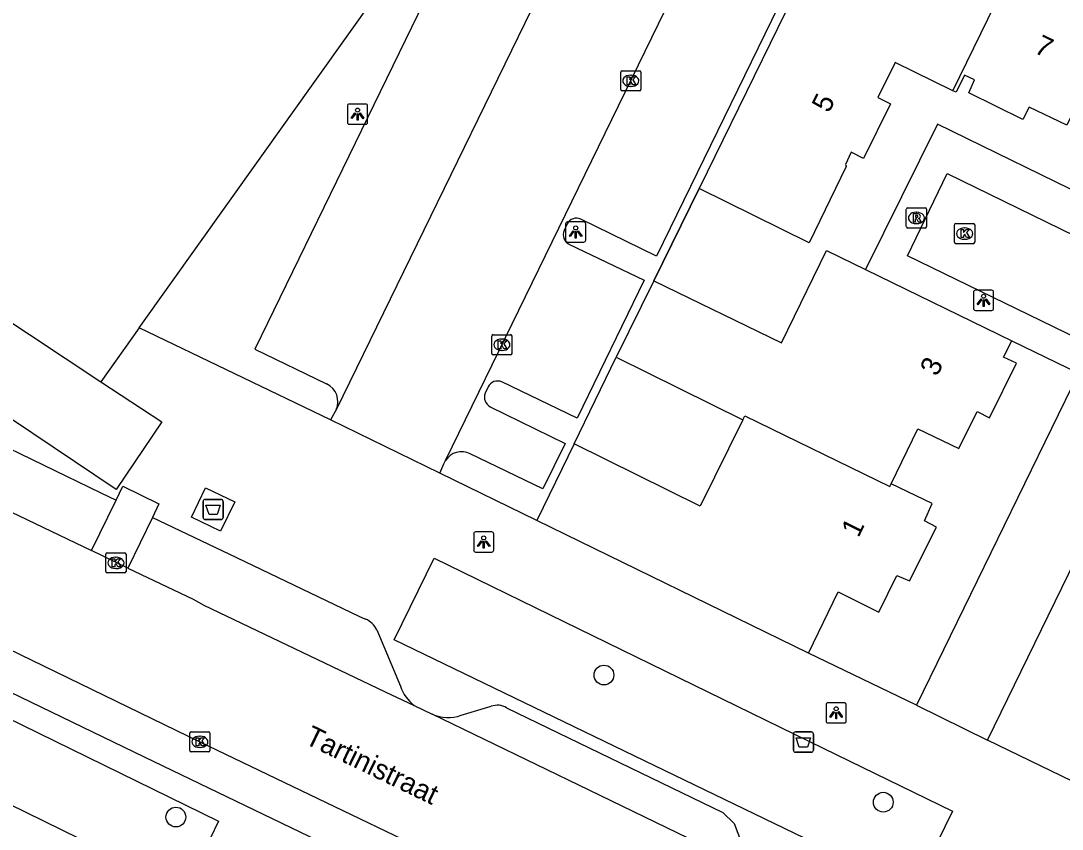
# Model space of a CAD drawing. Extents: x 159822 to 160765, y 380693 to 381634.
# Drawn here: x 160271.8 to 160323.3, y 381522.5 to 381562.5 of the extents above; entities that cross this region are included whole.
import ezdxf

# ---------------------------------------------------------------- set-up
doc = ezdxf.new("R2010")
doc.units = 0
for name, color, linetype in [('IMGEO_Afval_apart_plaats', 7, 'Continuous'), ('IMGEO_Afvalbak', 7, 'Continuous'), ('IMGEO_Boom', 7, 'Continuous'), ('IMGEO_Kolk', 7, 'Continuous'), ('IMGEO_Lichtpunt', 7, 'Continuous'), ('IMGEO_Muur', 7, 'Continuous'), ('IMGEO_Openbare_ruimte_label', 7, 'Continuous'), ('IMGEO_Pand', 7, 'Continuous'), ('IMGEO_Pand_nummerreeks', 7, 'Continuous'), ('IMGEO_Parkeervlak_gesloten', 7, 'Continuous'), ('IMGEO_Rijbaan_lokaal_open', 7, 'Continuous'), ('IMGEO_Rioolput', 7, 'Continuous'), ('IMGEO_Voetpad_gesloten', 7, 'Continuous'), ('IMGEO_Voetpad_open', 7, 'Continuous')]:
    doc.layers.add(name, color=color, linetype=linetype)

msp = doc.modelspace()

# ---------------------------------------------------------------- linework, layer by layer
at = {"layer": 'IMGEO_Afval_apart_plaats'}
for p, q in [((160280.815, 381537.912), (160280.815, 381538.712)), ((160280.815, 381538.712), (160280.815, 381537.912)), ((160280.915, 381538.812), (160281.705, 381538.812)), ((160281.705, 381538.812), (160280.915, 381538.812)), ((160281.805, 381538.712), (160281.805, 381537.912)), ((160281.805, 381537.912), (160281.805, 381538.712)), ((160281.705, 381537.812), (160280.915, 381537.812)), ((160280.915, 381537.812), (160281.705, 381537.812))]:
    msp.add_line(p, q, dxfattribs=at)
msp.add_lwpolyline([(160280.958, 381538.526), (160281.662, 381538.526), (160281.513, 381538.056), (160281.107, 381538.056), (160280.958, 381538.526)], dxfattribs=at)
for centre, start, end in [((160280.915, 381538.712), 90, 180), ((160280.915, 381538.712), 90, 180), ((160281.705, 381538.712), 0, 90), ((160281.705, 381538.712), 360, 90), ((160280.915, 381537.912), 180, 270), ((160280.915, 381537.912), 180, 270), ((160281.705, 381537.912), 270, 0), ((160281.705, 381537.912), 270, 0)]:
    msp.add_arc(centre, 0.1, start, end, dxfattribs=at)
at = {"layer": 'IMGEO_Afvalbak'}
for p, q in [((160310.035, 381526.396), (160310.035, 381527.196)), ((160310.035, 381527.196), (160310.035, 381526.396)), ((160310.135, 381527.296), (160310.925, 381527.296)), ((160310.925, 381527.296), (160310.135, 381527.296)), ((160311.025, 381527.196), (160311.025, 381526.396)), ((160311.025, 381526.396), (160311.025, 381527.196)), ((160310.925, 381526.296), (160310.135, 381526.296)), ((160310.135, 381526.296), (160310.925, 381526.296))]:
    msp.add_line(p, q, dxfattribs=at)
msp.add_lwpolyline([(160310.178, 381527.01), (160310.882, 381527.01), (160310.733, 381526.54), (160310.327, 381526.54), (160310.178, 381527.01)], dxfattribs=at)
for centre, start, end in [((160310.135, 381527.196), 90, 180), ((160310.135, 381527.196), 90, 180), ((160310.925, 381527.196), 0, 90), ((160310.925, 381527.196), 360, 90), ((160310.135, 381526.396), 180, 270), ((160310.135, 381526.396), 180, 270), ((160310.925, 381526.396), 270, 0), ((160310.925, 381526.396), 270, 0)]:
    msp.add_arc(centre, 0.1, start, end, dxfattribs=at)
at = {"layer": 'IMGEO_Boom'}
for centre in [(160300.659, 381530.116), (160314.484, 381523.82), (160279.467, 381523.086)]:
    msp.add_circle(centre, 0.489, dxfattribs=at)
at = {"layer": 'IMGEO_Kolk'}
for p, q in [((160301.488, 381559.108), (160301.488, 381559.96)), ((160301.563, 381560.034), (160302.415, 381560.034)), ((160301.976, 381559.814), (160302.001, 381559.814)), ((160302.489, 381559.96), (160302.489, 381559.108)), ((160301.999, 381559.254), (160301.974, 381559.254)), ((160302.415, 381559.034), (160301.563, 381559.034)), ((160318.013, 381551.545), (160318.013, 381552.397)), ((160318.088, 381552.471), (160318.94, 381552.471)), ((160319.014, 381552.397), (160319.014, 381551.545)), ((160318.501, 381552.251), (160318.526, 381552.251)), ((160318.94, 381551.471), (160318.088, 381551.471)), ((160318.524, 381551.691), (160318.499, 381551.691)), ((160295.105, 381546.041), (160295.105, 381546.893)), ((160295.18, 381546.967), (160296.032, 381546.967)), ((160295.593, 381546.747), (160295.618, 381546.747)), ((160296.106, 381546.893), (160296.106, 381546.041)), ((160295.616, 381546.187), (160295.591, 381546.187)), ((160296.032, 381545.967), (160295.18, 381545.967)), ((160275.998, 381535.243), (160275.998, 381536.095)), ((160276.073, 381536.169), (160276.925, 381536.169)), ((160276.486, 381535.949), (160276.511, 381535.949)), ((160276.999, 381536.095), (160276.999, 381535.243)), ((160276.509, 381535.389), (160276.484, 381535.389)), ((160276.925, 381535.169), (160276.073, 381535.169)), ((160280.153, 381526.382), (160280.153, 381527.234)), ((160280.228, 381527.308), (160281.08, 381527.308)), ((160280.641, 381527.088), (160280.666, 381527.088)), ((160281.154, 381527.234), (160281.154, 381526.382)), ((160281.08, 381526.308), (160280.228, 381526.308)), ((160280.664, 381526.528), (160280.639, 381526.528))]:
    msp.add_line(p, q, dxfattribs=at)
for points in [[(160301.488, 381559.108), (160301.488, 381559.96)], [(160301.563, 381560.034), (160302.415, 381560.034)], [(160301.809, 381559.734), (160301.932, 381559.734), (160301.932, 381559.583), (160302.062, 381559.734), (160302.226, 381559.734), (160302.08, 381559.583), (160302.233, 381559.334), (160302.081, 381559.334), (160301.996, 381559.498), (160301.932, 381559.431), (160301.932, 381559.334), (160301.809, 381559.334), (160301.809, 381559.734)], [(160302.489, 381559.96), (160302.489, 381559.108)], [(160302.415, 381559.034), (160301.563, 381559.034)], [(160318.013, 381551.545), (160318.013, 381552.397)], [(160318.088, 381552.471), (160318.94, 381552.471)], [(160319.014, 381552.397), (160319.014, 381551.545)], [(160318.334, 381552.171), (160318.457, 381552.171), (160318.457, 381552.02), (160318.587, 381552.171), (160318.751, 381552.171), (160318.605, 381552.02), (160318.758, 381551.771), (160318.606, 381551.771), (160318.521, 381551.935), (160318.457, 381551.868), (160318.457, 381551.771), (160318.334, 381551.771), (160318.334, 381552.171)], [(160318.94, 381551.471), (160318.088, 381551.471)], [(160295.105, 381546.041), (160295.105, 381546.893)], [(160295.18, 381546.967), (160296.032, 381546.967)], [(160296.106, 381546.893), (160296.106, 381546.041)], [(160295.426, 381546.667), (160295.549, 381546.667), (160295.549, 381546.516), (160295.679, 381546.667), (160295.843, 381546.667), (160295.697, 381546.516), (160295.85, 381546.267), (160295.698, 381546.267), (160295.613, 381546.431), (160295.549, 381546.364), (160295.549, 381546.267), (160295.426, 381546.267), (160295.426, 381546.667)], [(160296.032, 381545.967), (160295.18, 381545.967)], [(160275.998, 381535.243), (160275.998, 381536.095)], [(160276.073, 381536.169), (160276.925, 381536.169)], [(160276.319, 381535.869), (160276.442, 381535.869), (160276.442, 381535.718), (160276.572, 381535.869), (160276.736, 381535.869), (160276.59, 381535.718), (160276.743, 381535.469), (160276.591, 381535.469), (160276.506, 381535.633), (160276.442, 381535.566), (160276.442, 381535.469), (160276.319, 381535.469), (160276.319, 381535.869)], [(160276.999, 381536.095), (160276.999, 381535.243)], [(160276.925, 381535.169), (160276.073, 381535.169)], [(160280.153, 381526.382), (160280.153, 381527.234)], [(160280.228, 381527.308), (160281.08, 381527.308)], [(160281.154, 381527.234), (160281.154, 381526.382)], [(160280.474, 381527.008), (160280.597, 381527.008), (160280.597, 381526.857), (160280.727, 381527.008), (160280.891, 381527.008), (160280.745, 381526.857), (160280.898, 381526.608), (160280.746, 381526.608), (160280.661, 381526.772), (160280.597, 381526.705), (160280.597, 381526.608), (160280.474, 381526.608), (160280.474, 381527.008)], [(160281.08, 381526.308), (160280.228, 381526.308)]]:
    msp.add_lwpolyline(points, dxfattribs=at)
for centre, start, end in [((160301.565, 381559.958), 91.552, 178.448), ((160301.565, 381559.958), 91.552, 178.448), ((160302.413, 381559.958), 1.552, 88.448), ((160302.413, 381559.958), 1.552, 88.448), ((160301.565, 381559.11), 181.552, 268.448), ((160301.565, 381559.11), 181.552, 268.448), ((160302.413, 381559.11), 271.552, 358.448), ((160302.413, 381559.11), 271.552, 358.448), ((160318.09, 381552.395), 91.552, 178.448), ((160318.09, 381552.395), 91.552, 178.448), ((160318.938, 381552.395), 1.552, 88.448), ((160318.938, 381552.395), 1.552, 88.448), ((160318.09, 381551.547), 181.552, 268.448), ((160318.09, 381551.547), 181.552, 268.448), ((160318.938, 381551.547), 271.552, 358.448), ((160318.938, 381551.547), 271.552, 358.448), ((160295.182, 381546.891), 91.552, 178.448), ((160295.182, 381546.891), 91.552, 178.448), ((160296.03, 381546.891), 1.552, 88.448), ((160296.03, 381546.891), 1.552, 88.448), ((160295.182, 381546.043), 181.552, 268.448), ((160295.182, 381546.043), 181.552, 268.448), ((160296.03, 381546.043), 271.552, 358.448), ((160296.03, 381546.043), 271.552, 358.448), ((160276.075, 381536.093), 91.552, 178.448), ((160276.075, 381536.093), 91.552, 178.448), ((160276.923, 381536.093), 1.552, 88.448), ((160276.923, 381536.093), 1.552, 88.448), ((160276.075, 381535.245), 181.552, 268.448), ((160276.075, 381535.245), 181.552, 268.448), ((160276.923, 381535.245), 271.552, 358.448), ((160276.923, 381535.245), 271.552, 358.448), ((160280.23, 381527.232), 91.552, 178.448), ((160280.23, 381527.232), 91.552, 178.448), ((160281.078, 381527.232), 1.552, 88.448), ((160281.078, 381527.232), 1.552, 88.448), ((160280.23, 381526.384), 181.552, 268.448), ((160280.23, 381526.384), 181.552, 268.448), ((160281.078, 381526.384), 271.552, 358.448), ((160281.078, 381526.384), 271.552, 358.448)]:
    msp.add_arc(centre, 0.0765, start, end, dxfattribs=at)
for centre, major_axis, ratio, start_param, end_param in [((160301.975, 381559.534), (-0.387, 0.002), 0.722429, 4.712389, 7.853982), ((160302, 381559.534), (-0.39, 0.002), 0.717154, 1.570796, 4.712389), ((160318.5, 381551.971), (-0.387, 0.002), 0.722429, 4.712389, 7.853982), ((160318.525, 381551.971), (-0.39, 0.002), 0.717154, 1.570796, 4.712389), ((160295.592, 381546.467), (-0.387, 0.002), 0.722429, 4.712389, 7.853982), ((160295.617, 381546.467), (-0.39, 0.002), 0.717154, 1.570796, 4.712389), ((160276.485, 381535.669), (-0.387, 0.002), 0.722429, 4.712389, 7.853982), ((160276.51, 381535.669), (-0.39, 0.002), 0.717154, 1.570796, 4.712389), ((160280.64, 381526.808), (-0.387, 0.002), 0.722429, 4.712389, 7.853982), ((160280.665, 381526.808), (-0.39, 0.002), 0.717154, 1.570796, 4.712389)]:
    msp.add_ellipse(centre, major_axis=major_axis, ratio=ratio, start_param=start_param, end_param=end_param, dxfattribs=at)
at = {"layer": 'IMGEO_Lichtpunt'}
for p, q in [((160287.96, 381558.288), (160287.96, 381557.481)), ((160287.96, 381558.288), (160287.96, 381557.481)), ((160288.862, 381558.383), (160288.054, 381558.383)), ((160288.862, 381558.383), (160288.054, 381558.383)), ((160288.956, 381557.481), (160288.956, 381558.288)), ((160288.956, 381557.481), (160288.956, 381558.288)), ((160288.054, 381557.387), (160288.862, 381557.387)), ((160288.054, 381557.387), (160288.862, 381557.387)), ((160298.762, 381552.451), (160298.762, 381551.644)), ((160298.762, 381552.451), (160298.762, 381551.644)), ((160299.664, 381552.546), (160298.856, 381552.546)), ((160299.664, 381552.546), (160298.856, 381552.546)), ((160299.758, 381551.644), (160299.758, 381552.451)), ((160299.758, 381551.644), (160299.758, 381552.451)), ((160298.856, 381551.55), (160299.664, 381551.55)), ((160298.856, 381551.55), (160299.664, 381551.55)), ((160318.95, 381549.073), (160318.95, 381548.266)), ((160318.95, 381549.073), (160318.95, 381548.266)), ((160319.852, 381549.168), (160319.044, 381549.168)), ((160319.852, 381549.168), (160319.044, 381549.168)), ((160319.946, 381548.266), (160319.946, 381549.073)), ((160319.946, 381548.266), (160319.946, 381549.073)), ((160319.044, 381548.172), (160319.852, 381548.172)), ((160319.044, 381548.172), (160319.852, 381548.172)), ((160294.209, 381537.103), (160294.209, 381536.296)), ((160294.209, 381537.103), (160294.209, 381536.296)), ((160295.111, 381537.198), (160294.303, 381537.198)), ((160295.111, 381537.198), (160294.303, 381537.198)), ((160295.205, 381536.296), (160295.205, 381537.103)), ((160295.205, 381536.296), (160295.205, 381537.103)), ((160294.303, 381536.202), (160295.111, 381536.202)), ((160294.303, 381536.202), (160295.111, 381536.202)), ((160311.655, 381528.647), (160311.655, 381527.84)), ((160311.655, 381528.647), (160311.655, 381527.84)), ((160312.557, 381528.742), (160311.749, 381528.742)), ((160312.557, 381528.742), (160311.749, 381528.742)), ((160312.651, 381527.84), (160312.651, 381528.647)), ((160312.651, 381527.84), (160312.651, 381528.647)), ((160311.749, 381527.746), (160312.557, 381527.746)), ((160311.749, 381527.746), (160312.557, 381527.746))]:
    msp.add_line(p, q, dxfattribs=at)
for points in [[(160288.334, 381557.952), (160288.373, 381557.924), (160288.185, 381557.662), (160288.147, 381557.689), (160288.334, 381557.952)], [(160288.436, 381557.904), (160288.483, 381557.904), (160288.483, 381557.582), (160288.436, 381557.582), (160288.436, 381557.904)], [(160288.546, 381557.924), (160288.584, 381557.951), (160288.771, 381557.689), (160288.732, 381557.661), (160288.546, 381557.924)], [(160299.136, 381552.115), (160299.175, 381552.087), (160298.987, 381551.825), (160298.949, 381551.852), (160299.136, 381552.115)], [(160299.238, 381552.067), (160299.285, 381552.067), (160299.285, 381551.745), (160299.238, 381551.745), (160299.238, 381552.067)], [(160299.348, 381552.087), (160299.386, 381552.114), (160299.573, 381551.852), (160299.534, 381551.824), (160299.348, 381552.087)], [(160319.324, 381548.737), (160319.363, 381548.709), (160319.175, 381548.447), (160319.137, 381548.474), (160319.324, 381548.737)], [(160319.536, 381548.709), (160319.574, 381548.736), (160319.761, 381548.474), (160319.722, 381548.446), (160319.536, 381548.709)], [(160319.426, 381548.689), (160319.473, 381548.689), (160319.473, 381548.367), (160319.426, 381548.367), (160319.426, 381548.689)], [(160294.583, 381536.767), (160294.622, 381536.739), (160294.434, 381536.477), (160294.396, 381536.504), (160294.583, 381536.767)], [(160294.685, 381536.719), (160294.732, 381536.719), (160294.732, 381536.397), (160294.685, 381536.397), (160294.685, 381536.719)], [(160294.795, 381536.739), (160294.833, 381536.766), (160295.02, 381536.504), (160294.981, 381536.476), (160294.795, 381536.739)], [(160312.029, 381528.311), (160312.068, 381528.283), (160311.88, 381528.021), (160311.842, 381528.048), (160312.029, 381528.311)], [(160312.131, 381528.263), (160312.178, 381528.263), (160312.178, 381527.941), (160312.131, 381527.941), (160312.131, 381528.263)], [(160312.241, 381528.283), (160312.279, 381528.31), (160312.466, 381528.048), (160312.427, 381528.02), (160312.241, 381528.283)]]:
    msp.add_lwpolyline(points, dxfattribs=at)
for centre in [(160288.459, 381558.086), (160299.261, 381552.249), (160319.449, 381548.871), (160294.708, 381536.901), (160312.154, 381528.445)]:
    msp.add_circle(centre, 0.0994, dxfattribs=at)
for centre, start, end in [((160288.054, 381558.288), 90, 180), ((160288.054, 381558.288), 90, 180), ((160288.862, 381558.288), 0, 90), ((160288.862, 381558.288), 0, 90), ((160288.054, 381557.481), 180, 270), ((160288.054, 381557.481), 180, 270), ((160288.862, 381557.481), 270, 0), ((160288.862, 381557.481), 270, 360), ((160298.856, 381552.451), 90, 180), ((160298.856, 381552.451), 90, 180), ((160299.664, 381552.451), 0, 90), ((160299.664, 381552.451), 0, 90), ((160298.856, 381551.644), 180, 270), ((160298.856, 381551.644), 180, 270), ((160299.664, 381551.644), 270, 0), ((160299.664, 381551.644), 270, 360), ((160319.044, 381549.073), 90, 180), ((160319.044, 381549.073), 90, 180), ((160319.852, 381549.073), 0, 90), ((160319.852, 381549.073), 0, 90), ((160319.044, 381548.266), 180, 270), ((160319.044, 381548.266), 180, 270), ((160319.852, 381548.266), 270, 0), ((160319.852, 381548.266), 270, 360), ((160294.303, 381537.103), 90, 180), ((160294.303, 381537.103), 90, 180), ((160295.111, 381537.103), 0, 90), ((160295.111, 381537.103), 0, 90), ((160294.303, 381536.296), 180, 270), ((160294.303, 381536.296), 180, 270), ((160295.111, 381536.296), 270, 0), ((160295.111, 381536.296), 270, 360), ((160311.749, 381528.647), 90, 180), ((160311.749, 381528.647), 90, 180), ((160312.557, 381528.647), 0, 90), ((160312.557, 381528.647), 0, 90), ((160311.749, 381527.84), 180, 270), ((160311.749, 381527.84), 180, 270), ((160312.557, 381527.84), 270, 0), ((160312.557, 381527.84), 270, 360)]:
    msp.add_arc(centre, 0.0946, start, end, dxfattribs=at)
at = {"layer": 'IMGEO_Muur'}
for points in [[(160303.125, 381549.631), (160305.365, 381554.212)], [(160299.181, 381541.556), (160301.262, 381545.859)]]:
    msp.add_lwpolyline(points, dxfattribs=at)
at = {"layer": 'IMGEO_Pand'}
for points in [[(160277.654, 381547.301), (160296.723, 381574.075), (160306.244, 381587.443)], [(160317.933, 381559.045), (160322.802, 381569.021)], [(160311.603, 381566.955), (160305.365, 381554.212)], [(160317.933, 381559.045), (160315.068, 381560.434), (160314.21, 381558.715), (160314.846, 381558.397), (160313.515, 381555.686), (160312.894, 381556.002), (160312.611, 381555.392), (160312.657, 381555.291), (160310.816, 381551.506), (160305.365, 381554.212)], [(160327.277, 381558.053), (160324.541, 381559.364), (160323.565, 381557.338), (160321.716, 381558.227), (160321.402, 381557.626), (160318.722, 381558.946), (160319, 381559.581), (160318.515, 381559.808), (160318.087, 381558.97), (160317.933, 381559.045)], [(160303.125, 381549.631), (160309.443, 381546.559), (160311.681, 381551.141), (160313.61, 381550.198)], [(160313.61, 381550.198), (160320.845, 381546.663)], [(160303.125, 381549.631), (160301.262, 381545.859)], [(160270.432, 381548.143), (160275.755, 381544.635)], [(160277.654, 381547.301), (160275.755, 381544.635)], [(160314.881, 381539.581), (160316.193, 381542.305), (160318.224, 381541.325), (160319.126, 381543.156), (160319.74, 381542.844), (160321.078, 381545.56), (160320.438, 381545.851), (160320.845, 381546.663)], [(160301.262, 381545.859), (160307.534, 381542.75)], [(160307.534, 381542.75), (160305.423, 381538.472), (160299.181, 381541.556)], [(160307.534, 381542.75), (160307.631, 381542.946), (160314.816, 381539.447), (160314.881, 381539.581)], [(160299.181, 381541.556), (160297.344, 381537.77)], [(160310.78, 381531.204), (160312.257, 381534.229), (160314.263, 381533.224), (160315.164, 381535.052), (160315.783, 381534.785), (160317.117, 381537.445), (160316.533, 381537.749), (160316.912, 381538.604), (160314.881, 381539.581)], [(160310.78, 381531.204), (160297.344, 381537.77)]]:
    msp.add_lwpolyline(points, dxfattribs=at)
at = {"layer": 'IMGEO_Parkeervlak_gesloten'}
for points in [[(160275.289, 381536.28), (160276.51, 381538.779)], [(160278.302, 381537.923), (160277.097, 381535.415)]]:
    msp.add_lwpolyline(points, dxfattribs=at)
at = {"layer": 'IMGEO_Rijbaan_lokaal_open'}
for points in [[(160317.098, 381587.902), (160301.512, 381571.66), (160301.091, 381571.17), (160300.753, 381570.625), (160287.403, 381543.245)], [(160292.813, 381540.736), (160305.669, 381567.115), (160306.528, 381568.286), (160308.882, 381570.766), (160313.898, 381575.449)], [(160319.643, 381526.897), (160328.335, 381544.714), (160315.686, 381550.873), (160317.652, 381554.951), (160332.391, 381547.759), (160347.209, 381540.529), (160345.228, 381536.493), (160332.547, 381542.69), (160323.844, 381524.858)], [(160287.403, 381543.245), (160287.125, 381542.749)], [(160292.539, 381540.113), (160287.125, 381542.749)], [(160263.322, 381542.008), (160275.289, 381536.28)], [(160292.539, 381540.113), (160292.732, 381540.57), (160292.813, 381540.736)], [(160259.046, 381537.25), (160262.208, 381535.767), (160280.654, 381526.809), (160297.771, 381518.588), (160305.928, 381514.619)], [(160277.097, 381535.415), (160275.289, 381536.28)], [(160277.097, 381535.415), (160280.318, 381533.873), (160280.849, 381533.572), (160289.833, 381529.291), (160291.263, 381528.602)], [(160291.263, 381528.602), (160292.148, 381528.177)], [(160308.671, 381520.176), (160299.919, 381524.408), (160292.148, 381528.177)], [(160323.844, 381524.858), (160319.643, 381526.897)]]:
    msp.add_lwpolyline(points, dxfattribs=at)
at = {"layer": 'IMGEO_Rioolput'}
for p, q in [((160315.627, 381552.322), (160315.627, 381553.174)), ((160315.702, 381553.248), (160316.554, 381553.248)), ((160316.115, 381553.028), (160316.14, 381553.028)), ((160316.628, 381553.174), (160316.628, 381552.322)), ((160316.138, 381552.468), (160316.113, 381552.468)), ((160316.554, 381552.248), (160315.702, 381552.248))]:
    msp.add_line(p, q, dxfattribs=at)
for points in [[(160315.627, 381552.322), (160315.627, 381553.174)], [(160315.702, 381553.248), (160316.554, 381553.248)], [(160316.216, 381552.946), (160315.964, 381552.948), (160315.964, 381552.548)], [(160316.142, 381552.867), (160316.088, 381552.867), (160316.088, 381552.786)], [(160316.628, 381553.174), (160316.628, 381552.322)], [(160315.964, 381552.548), (160316.088, 381552.548), (160316.088, 381552.71), (160316.099, 381552.71)], [(160316.088, 381552.786), (160316.14, 381552.786)], [(160316.146, 381552.681), (160316.217, 381552.548), (160316.357, 381552.548), (160316.292, 381552.674)], [(160316.554, 381552.248), (160315.702, 381552.248)]]:
    msp.add_lwpolyline(points, dxfattribs=at)
for centre, radius, start, end in [((160315.704, 381553.172), 0.0765, 91.552, 178.448), ((160315.704, 381553.172), 0.0765, 91.552, 178.448), ((160316.148, 381552.771), 0.0964, 77.0061, 93.1865), ((160316.162, 381552.828), 0.0378, 276.6634, 79.6772), ((160316.215, 381552.836), 0.109, 350.3612, 89.416), ((160316.552, 381553.172), 0.0765, 1.552, 88.448), ((160316.552, 381553.172), 0.0765, 1.552, 88.448), ((160316.098, 381552.657), 0.0533, 26.0293, 88.6989), ((160316.124, 381552.975), 0.19, 274.7715, 282.9687), ((160316.213, 381552.836), 0.112, 277.5842, 350.9817), ((160316.197, 381552.621), 0.108, 29.5134, 73.7905), ((160315.704, 381552.324), 0.0765, 181.552, 268.448), ((160315.704, 381552.324), 0.0765, 181.552, 268.448), ((160316.552, 381552.324), 0.0765, 271.552, 358.448), ((160316.552, 381552.324), 0.0765, 271.552, 358.448)]:
    msp.add_arc(centre, radius, start, end, dxfattribs=at)
for centre, major_axis, ratio, start_param, end_param in [((160316.114, 381552.748), (-0.387, 0.002), 0.722429, 4.712389, 7.853982), ((160316.139, 381552.748), (-0.39, 0.002), 0.717154, 1.570796, 4.712389)]:
    msp.add_ellipse(centre, major_axis=major_axis, ratio=ratio, start_param=start_param, end_param=end_param, dxfattribs=at)
at = {"layer": 'IMGEO_Voetpad_gesloten'}
for points in [[(160275.755, 381544.635), (160278.775, 381542.651), (160276.508, 381539.306), (160268.201, 381544.872), (160270.432, 381548.143)], [(160282.381, 381538.686), (160281.681, 381537.24), (160280.24, 381537.937), (160280.94, 381539.383), (160282.381, 381538.686)]]:
    msp.add_lwpolyline(points, dxfattribs=at)
at = {"layer": 'IMGEO_Voetpad_open'}
for points in [[(160308.799, 381567.721), (160310.97, 381566.672), (160303.259, 381550.859), (160299.518, 381552.682)], [(160295.333, 381565.687), (160293.317, 381566.669), (160283.375, 381546.248), (160286.927, 381544.531)], [(160345.895, 381534.462), (160349.444, 381541.616), (160333.242, 381549.532), (160317.168, 381557.385), (160313.61, 381550.198)], [(160305.365, 381554.212), (160303.125, 381549.631)], [(160298.834, 381552.449), (160298.69, 381552.119)], [(160298.928, 381551.444), (160302.652, 381549.663), (160299.336, 381542.835), (160295.599, 381544.63)], [(160254.321, 381549.203), (160260.099, 381546.679), (160260.887, 381546.335), (160267.172, 381543.293), (160275.746, 381539.144), (160276.51, 381538.779)], [(160287.125, 381542.749), (160277.654, 381547.301)], [(160320.845, 381546.663), (160324.15, 381545.059), (160316.129, 381528.616)], [(160299.181, 381541.556), (160301.262, 381545.859)], [(160294.925, 381544.38), (160294.775, 381544.068)], [(160295.026, 381543.4), (160298.737, 381541.581), (160297.629, 381539.334), (160294.034, 381541.065)], [(160297.344, 381537.77), (160292.539, 381540.113)], [(160276.51, 381538.779), (160276.849, 381539.474), (160278.626, 381538.598), (160278.302, 381537.923)], [(160278.302, 381537.923), (160282.096, 381536.111), (160288.531, 381533.032), (160288.861, 381532.887)], [(160315.98, 381519.427), (160309.588, 381522.519), (160290.271, 381531.865), (160292.261, 381535.907), (160311.513, 381526.497), (160317.905, 381523.372), (160315.98, 381519.427)], [(160302.085, 381514.381), (160296.96, 381516.87), (160277.913, 381526.048), (160260.5, 381534.459)], [(160289.408, 381532.352), (160290.582, 381529.56)], [(160316.129, 381528.616), (160310.78, 381531.204)], [(160293.587, 381528.124), (160295.082, 381528.568)], [(160295.831, 381528.497), (160306.55, 381523.313), (160307.102, 381522.764), (160307.652, 381521.324)], [(160316.129, 381528.616), (160319.643, 381526.897)], [(160279.929, 381519.451), (160269.443, 381524.578), (160271.037, 381528.046), (160281.582, 381522.879), (160279.929, 381519.451)]]:
    msp.add_lwpolyline(points, dxfattribs=at)
for centre, radius, start, end in [((160299.293, 381552.223), 0.512, 63.8747, 153.7475), ((160299.175, 381551.91), 0.528, 156.7041, 242.1404), ((160295.393, 381544.152), 0.521, 66.6965, 154.0052), ((160286.507, 381543.644), 0.981, 335.972, 64.651), ((160295.286, 381543.879), 0.545, 159.6855, 241.5017), ((160293.601, 381540.242), 0.93, 62.2413, 147.9192), ((160288.404, 381531.873), 1.112, 25.5109, 65.76), ((160292.588, 381530.265), 2.126, 199.363, 231.4517), ((160292.932, 381529.909), 1.901, 245.637, 290.1444), ((160295.384, 381527.765), 0.858, 58.5651, 110.6047)]:
    msp.add_arc(centre, radius, start, end, dxfattribs=at)

# ---------------------------------------------------------------- texts
at = {"layer": 'IMGEO_Openbare_ruimte_label'}
msp.add_text('Tartinistraat', height=1, rotation=334.204, dxfattribs=at).set_placement((160285.789, 381526.75))
at = {"layer": 'IMGEO_Pand_nummerreeks'}
for s, rotation, p in [('7', 333.9363, (160321.9, 381560.957)), ('5', 63.8504, (160311.797, 381557.905)), ('3', 63.8486, (160317.151, 381544.857)), ('1', 63.7853, (160313.256, 381536.882))]:
    msp.add_text(s, height=1, rotation=rotation, dxfattribs=at).set_placement(p)

doc.saveas('drawing.dxf')
